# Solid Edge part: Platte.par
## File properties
Username: bmolnar
Dokumentum tartalom típus: 0
Author: bmolnar
Last saved by: bmolnar
Revision: 83
Sűrűség: 0,000 kg/m^3
Pontosság: 0,990
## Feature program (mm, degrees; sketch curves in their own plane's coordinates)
base feature "unnamed BaseFeature 1"
sketch for "unnamed Hole 1" plane through (0, 0, -197) normal (0, 0, -1) x-axis (0, 1, 0)
  hole centre (-15, 52) bore radius 3.3235
hole "unnamed Hole 1"
sketch for "unnamed Hole 2" plane through (0, 0, -197) normal (0, 0, -1) x-axis (0, 1, 0)
  hole centre (15, 52) bore radius 3.3235
hole "unnamed Hole 2"
sketch for "unnamed Hole 3" plane through (0, 0, -197) normal (0, 0, -1) x-axis (0, 1, 0)
  hole centre (15, -52) bore radius 3.3235
hole "unnamed Hole 3"
sketch for "unnamed Hole 4" plane through (0, 0, -197) normal (0, 0, -1) x-axis (0, 1, 0)
  hole centre (-15, -52) bore radius 3.3235
hole "unnamed Hole 4"
pattern "unnamed Pattern 1" of "unnamed Hole 1", "unnamed Hole 2", "unnamed Hole 3", "unnamed Hole 4"
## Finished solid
Body 1: solid body, 64 faces, 119 edges, 55 vertices.
  Faces by surface: plane 38, cylinder 17, cone 6, torus 3
  Edges by curve: line 56, circle 40, spline 21, ellipse 2
Bounding box of the edges (mm; curved faces can reach further): 118.000 x 45.000 x 302.000, from (-59, -22.5, -197) to (59, 22.5, 105).
Cylindrical faces by radius (mm): R2 x2, R3.3235 x4, R5 x1, R5.25 x1, R5.75 x1, R6 x1, R6.5 x2, R6.75 x2, R10 x2, R20 x1
Conical faces (half-angle, radius in mm at the cone's reference point): 30 deg R5.875 x1, 45 deg R10 x2, 60 deg R1.1547 x1, 60 deg R1.4434 x2
Toroidal faces (ring radius, tube radius in mm): R4.4 r0.6 x1, R5.7 r0.8 x2
Planar faces by outward normal: +x 1, +y 2, +z 4, -x 1, -y 2, -z 8, oblique 20
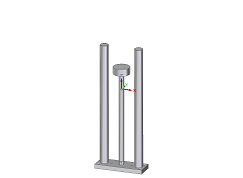
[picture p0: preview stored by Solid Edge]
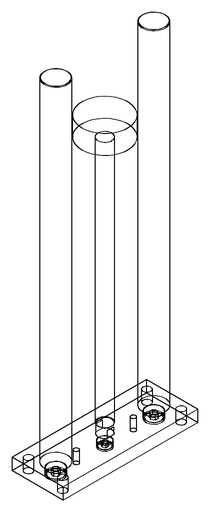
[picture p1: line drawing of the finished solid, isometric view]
